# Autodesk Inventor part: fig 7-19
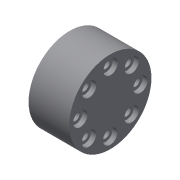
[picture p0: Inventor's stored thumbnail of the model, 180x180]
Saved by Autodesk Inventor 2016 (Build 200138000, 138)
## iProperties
Created: 2004-05
Part Number: fig 7-19
Document SubType Name: Modeling
Designer: CADCIM Technologies
Manufacturer: Standard
Standards Organization: Custom
Density: 1 g/cm^3
Material: Generic
Appearance: Default
Author: CADCIM Technologies
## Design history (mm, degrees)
sketch "Sketch1"
  geometry: C1 r 17.175 at (0, 0)
  constraints: 1 centre point
extrude "Extrusion1" new body sketch "Sketch1" distance "d0" = 17; taper "d1" = 0 deg
sketch "Sketch2"
  geometry: 1 further point
hole "Hole1" sketch "Sketch2" at (12.571, -0.074) diameter "d2" = 3.5; stored, may be unused: countersink angle "d6" = 90 deg, drill point angle "d8" = 118 deg; dims "d3" = 6, "d4" = 6, "d5" = 2, "d7" = 8
pattern_circular "Circular Pattern1" dims angle "d11" = 360 deg
body "Solid1"
